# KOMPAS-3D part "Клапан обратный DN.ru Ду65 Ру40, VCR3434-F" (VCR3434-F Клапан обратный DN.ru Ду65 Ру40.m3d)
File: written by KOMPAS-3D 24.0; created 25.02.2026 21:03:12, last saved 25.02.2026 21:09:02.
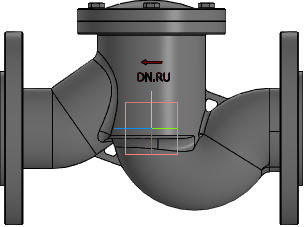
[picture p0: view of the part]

Document properties: Автор: R2D2; Полное имя файла: VCR3434-F Клапан обратный DN.ru Ду65 Ру40.cdw

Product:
- Part/product: Клапан обратный DN.ru Ду65 Ру40  | designation VCR3434-F
    Масса: 16
    Раздел спецификации: Прочие изделия
    Форматы листов документа: A2
    Примечание: D100-04056
    additional columns: D100-04056

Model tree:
1. Операция без истории:1
2. Элемент выдавливания:1  (with: Грань.Операция без истории:1)
     Расстояние 1 = 36.2449
3. Эскиз:1  (with: Грань.Операция без истории:1, Ребро.Операция без истории:1)
4. Элемент выдавливания:2
     Расстояние 1 = 11

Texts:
  Точка начала. Х
  Точка начала. Y
  Точка начала. Z
  VCR3434-F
